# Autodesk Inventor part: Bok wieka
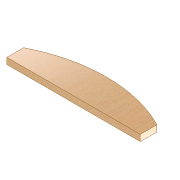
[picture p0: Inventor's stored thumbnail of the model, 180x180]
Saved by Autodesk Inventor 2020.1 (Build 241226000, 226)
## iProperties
Created: 2005-09
Part Number: Bok wieka
Document SubType Name: Modeling
Designer: F.Stasiak
Density: 1 g/cm^3
Material: Ogólny
Appearance: Sosna żółta — pełna — barwiona na jasno — niski połysk
Manager: www.cadconsulting.pl
Company: Fabian Stasiak CAD Consulting
Author: F.Stasiak
Subject: Zbiór ćwiczeń. Autodesk Inventor 2020. Kurs podstawowy
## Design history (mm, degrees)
sketch "Szkic1"
  geometry: L1 (-160, 40)-(-160, 0); L2 (-160, 0)-(160, 0); L3 (160, 0)-(160, 40); A1 r 350 centre (0, -271.288) between (160, 40) and (-160, 40); 2 further points
  constraints: 6 end point, 2 parallel, 2 point on circle, 1 centre point, 1 coincident, 1 midpoint, 1 perpendicular, 1 vertical
  dimensions: "d0" = 40 distance of L1.start L1.end; "d1" = 320 distance of L1.end L2.end; "d2" = 350 radius of A1
extrude "Wyciągnięcie proste1" new body sketch "Szkic1" stored distance "d3" = 15; taper "d4" = 0 deg
node "Bryła1"
node "Korpusy bryłowe"
node "Korpusy powierzchniowe"
